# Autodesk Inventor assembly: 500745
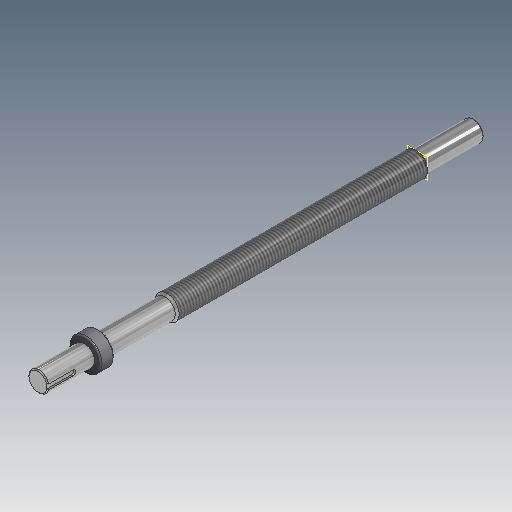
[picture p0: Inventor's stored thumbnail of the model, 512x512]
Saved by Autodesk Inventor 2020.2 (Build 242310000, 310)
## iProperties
Created: 2000-03
Part Number: 500745
Document SubType Name: Assembly
Designer: sspink
Mass: 1381.74 g
Surface Area: 341.517 cm^2
Volume: 176.442 cm^3
Density: 7.83115 g/cm^3
Control State: 0
Master: False
Checked Out: False
Shininess: 0.0
Length Units: 11269
Angle Units: 11279
Time Units: 11290
Mass Units: 11283
Length Display Precision: 3
Angle Display Precision: 2
Compacted: True
Dimensions: 32x432x32 mm
Mass: 1,382 kg
DocNumber: 500745.iam
Folder: 01 - Themengebiete\Simplification\01 - Packaging machine\
VDS_Category: 3D Komponenten
Density: 0.0
Volumn: 0.0
Area: 0.0
PropertySet Name: Model Information
Author: sspink
Revision Number: -
Title: 500745
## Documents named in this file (3)
- D:\07 - DEMODATEN\OTX 2019 - Dataset - UPDATE - Dez2019\Designs\07-Packing machine\500745.iam
- D:\07 - DEMODATEN\OTX 2019 - Dataset - UPDATE - Dez2019\Designs\07-Packing machine\Parts\ADSK-011716.ipt
- D:\07 - DEMODATEN\OTX 2019 - Dataset - UPDATE - Dez2019\Designs\07-Packing machine\Parts\ADSK-011698.ipt
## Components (2 placed, 2 different names)
1. ADSK-011698:1 — Passend:1, Flush:1
2. ADSK-011716:1 — Passend:1, Flush:1
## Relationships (2: Mate 1, Flush 1)
- Passend:1 [Mate]: ADSK-011698:1 ↔ ADSK-011716:1
- Flush:1: ADSK-011698:1 ↔ ADSK-011716:1
